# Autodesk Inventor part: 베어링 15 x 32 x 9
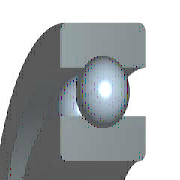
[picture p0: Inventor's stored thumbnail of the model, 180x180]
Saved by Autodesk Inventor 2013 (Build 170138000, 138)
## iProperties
IsCustomPart: 0
Created: 2012-02
Part Number: 베어링 15 x 32 x 9
Material: 강철, 연강
Description: 깊은 그루브 볼 베어링
Document SubType Name: Modeling
Standard: KS B 2023
Designer: mduedu
Standards Organization: KS
Language: ko-KR
Size Designation: 6002 - 15 x 32 x 9
Categories: <MemberInstance><Categories><Category DisplayName="샤프트 부품" InternalName="7f7aeb1f-a693-4053-b835-cee3144e0d98" Mnemonic="SHFT"><Category DisplayName="베어링" Inter
Density: 7.86 g/cm^3
Mass: 29.8124 g
Surface Area: 39.9079 cm^2
Volume: 3.79293 cm^3
Author: mduedu
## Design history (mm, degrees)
sketch "스케치" dims "d0" = 4.42 (= -0.26 x WD + 0.26 x BD)
  geometry: L1 (2.29, 11.75)-(6.71, 11.75); L2 (4.5, 11.75)-(4.5, 9.54); L3 (4.5, 11.75)-(4.5, 13.96); L4 (2.858, 10.271)-(0, 10.271); L5 (0, 7.5)-(9, 7.5); L6 (2.858, 13.229)-(0, 13.229); L7 (0, 16)-(9, 16); L8 (9, 7.5)-(9, 10.271); L9 (6.142, 10.271)-(9, 10.271); L10 (6.142, 13.229)-(9, 13.229); L11 (9, 16)-(9, 13.229); L12 (-1.4, 0)-(8.4, 0) reference; L13 (0, -0.3)-(0, 5.3) reference
  constraints: 22 end point, 4 point on line, 2 collinear, 2 perpendicular, 2 symmetric about line, 1 midpoint, 1 parallel, 14 other
  dimensions: "d9" = 15 diameter of L5 L12 (= WD); "d11" = 32 diameter of L7 L12 (= BD); "d12" = 9 distance between parallel lines of L8 L13 (= KB); "d13" = 20.542 diameter of L9 L12 (= 0.326 x BD + 0.674 x WD)
revolve "본체" stored, may be unused: angle "d6" = 90 deg
revolve "볼" stored, may be unused: angle "d7" = 90 deg
pattern_circular "IDS_ARRAYBALL[SIMPL:T]" dims angle "d3" = 360 deg
body "Solid1"
fillet "모깎기1" dims "d1" = 0.3 (= KRS)
other parameters: "WD" = 15 [user parameter; used in 5 equation terms], "BD" = 32 [user parameter; used in 5 equation terms], "KB" = 9 [user parameter; used in 1 equation term], "KRS" = 0.3 [user parameter; used in 1 equation term], "d4" = 0, "d5" = 0, "d8" = 0, "d14" = 0, "d15" = 0, "BBA" = 0 [user parameter], "BC0" = 2850000 [user parameter], "BC" = 5590000 [user parameter], "BR" = 16 (= 0.5 x BD) [user parameter], "WR" = 7.5 (= 0.5 x WD) [user parameter]
